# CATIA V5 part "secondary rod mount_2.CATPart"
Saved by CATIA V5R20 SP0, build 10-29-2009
Part number: secondary rod mount 2
Source: Unknown
Bounding box of the stored display mesh (mm): x 0 to 50, y -10 to 58.3, z -46 to 0
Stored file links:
  C:\Users\Ikarus\OneDrive - FH JOANNEUM\BAC - Arbeit 1\CAD Modell\CAD-Modell-Step files\rod mount\secondary\secondary rod mount_2.CATPart
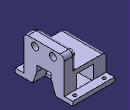
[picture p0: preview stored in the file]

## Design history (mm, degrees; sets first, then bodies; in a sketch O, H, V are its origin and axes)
Body1 (main body)
  Solid1 "Hauptkörper": solid without history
